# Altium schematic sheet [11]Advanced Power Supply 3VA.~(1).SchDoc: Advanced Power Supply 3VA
size A4; Organization: BQR; Address1: Reliability Engineering; Address2: Optimized Maintenance; Address3: www.bqr.com; Address4: www.bqr-digital.com; DocumentNumber: DOC12; SheetNumber: 7; SheetTotal: 13
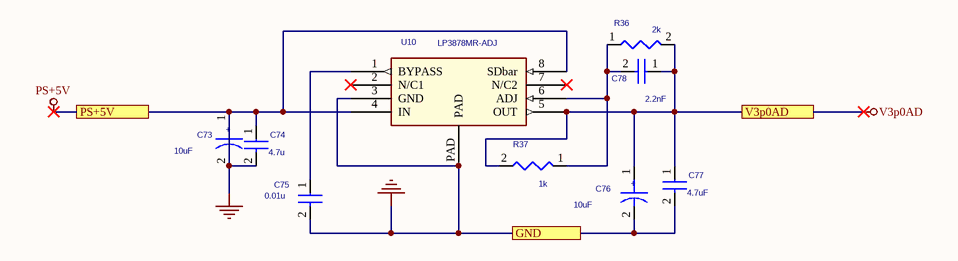
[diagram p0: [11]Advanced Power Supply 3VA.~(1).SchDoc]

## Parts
C73  10uF  [cap_c-case]
C74  4.7u  [0603]
C75  0.01u  [0603]
C76  10uF  [cap_c-case]
C77  4.7uF  [0603]
C78  2.2nF  [0603]
R36  2k  [0603]
R37  1k  [0603]
U10  LP3878MR-ADJ  [lp3878-adj_mra08a-psop]

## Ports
GND, PS+5V, V3p0AD

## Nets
GND: C73.1 C73.2 C74.1 C74.2 C75.2 C76.2 C77.2 U10.3(GND) U10.4(IN) U10.8(SDbar) U10.PAD ; port PS+5V, port GND  [also labelled PS+5V]
V3p0AD: C76.1 C77.1 C78.1 R36.2 R37.2 U10.5(OUT) ; port V3p0AD
NetC75_1: C75.1 U10.1(BYPASS)
NetC78_2: C78.2 R36.1 R37.1 U10.6(ADJ)

Not connected (* = marked no-connect by the designer): U10 2(N/C1)* 7(N/C2)*

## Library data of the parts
C73 = Cap_Polar_1: CAP TANT 10UF 20V 10% 2312; Manufacturer P/N: TAJC106K020R; Manufacturer: AVX; fiX_Manuf: Murata; Catalog Number: CAP00001; SDTA_I(Isurge): 0.001; SDTA_V(Voltage): 5; fiX_Func: Advanced Power Supply 3V (2)
C74 = Capacitor_3: CAP CER 4.7UF 6.3V X5R 0603; Manufacturer P/N: ECJ-1VB0J475M; Manufacturer: Panasonic; Catalog Number: CAP00017; SDTA_V(Voltage): 5; fiX_Func: Advanced Power Supply 3V (2)
C75 = Capacitor_3: CAP CER 10000PF 50V X7R 0603; Manufacturer P/N: ECJ-1VB1H103K; Manufacturer: Panasonic; fiX_Manuf: AVX; Catalog Number: CAP00018; fiX_Func: Advanced Power Supply 3V (2); SDTA_V(Voltage): 5
C76 = Cap_Polar_1: CAP TANT 10UF 20V 10% 2312; Manufacturer P/N: TAJC106K020R; Manufacturer: AVX; fiX_Manuf: Murata; Catalog Number: CAP00001; SDTA_V(Voltage): 3; fiX_Func: Advanced Power Supply 3V (2)
C77 = Capacitor_3: CAP CER 4.7UF 6.3V X5R 0603; Manufacturer: Panasonic; Manufacturer P/N: ECJ-1VB0J475M; Catalog Number: CAP00017; SDTA_V(Voltage): 3; fiX_Func: Advanced Power Supply 3V (2)
C78 = Cap_1: CAP CER 2200PF 50V X7R 0603; Manufacturer P/N: ECJ-1VB1H222K; Manufacturer: Panasonic; fiX_Manuf: Murata; Catalog Number: CAP00019; fiX_Func: Advanced Power Supply 3V (2)
R36 = Resistor_3: RES SMD 2K OHM 1% 1/10W 0603; Manufacturer P/N: CRCW06032K00FKEA; Manufacturer: Vishay; Catalog Number: RES00011; fiX_Func: Advanced Power Supply 3V (2)
R37 = Resistor_3: RES SMD 1K OHM 1% 1/10W 0603; Manufacturer P/N: CRCW06031K00FKEA; Manufacturer: Vishay; Catalog Number: RES00010; fiX_Func: Advanced Power Supply 3V (2)
U10 = LP3878MR-ADJ_5: Linear Voltage Regulator IC Positive Adjustable 1 Output 1 V ~ 5.5 V 800mA 8-SO PowerPad; Manufacturer P/N: LP3878MR-ADJ/NOPB; Manufacturer: Texas Instruments; Catalog Number: IC00030; fiX_Func: Advanced Power Supply 3V (2)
